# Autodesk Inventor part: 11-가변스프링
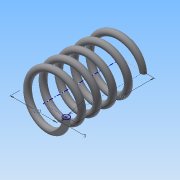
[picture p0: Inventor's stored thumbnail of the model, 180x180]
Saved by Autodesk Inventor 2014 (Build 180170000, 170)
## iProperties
Created: 2015-09
Part Number: 11-가변스프링
Material: 강철, 탄소
Document SubType Name: Modeling
Designer: study
Density: 1 g/cm^3
Appearance: 반연마
Author: study
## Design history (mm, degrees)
sketch "스케치1"
  geometry: L1 (0, 0)-(11, 0); L2 (11, 0)-(11, 25.208); L3 (11, 25.208)-(0, 25.208); L4 (0, 25.208)-(0, 0); C1 r 1.5 at (11, 0)
  constraints: 8 end point, 2 parallel, 1 centre point, 1 coincident, 1 horizontal, 1 perpendicular
  dimensions: "d0" = 3 diameter of C1; "d1" = 22 diameter of L1.end L4; "d2" = 25.20829 distance of L1.end L2.end (derived)
feature "코일1" sketch "스케치1" pitch "d3" = 10; turns "d5" = 5; dims "d4" = 25.20829 (= d2), "d6" = 0, angle "d7" = 90 deg, angle "d8" = 90 deg, "d9" = 0, "d10" = 0
node "작업 평면1"
sketch "스케치2"
  geometry: L1 (-12.5, 0)-(-9.5, 0) reference; 1 further point
  constraints: 1 horizontal alignment
extrude "돌출1" cut sketch "스케치2" stored distance "d12" = 10; taper "d13" = 0 deg
node "작업 평면2"
sketch "스케치3"
  geometry: L1 (-9.5, 0)-(-12.5, 0) reference; 1 further point
  constraints: 1 horizontal alignment
extrude "돌출2" cut sketch "스케치3" stored distance "d15" = 10; taper "d16" = 0 deg
node "솔리드1"
node "절단 모서리 투영1"
node "절단 모서리 투영2"
other parameters: "d11" = 0, "d14" = 25.20829 (= d2)
